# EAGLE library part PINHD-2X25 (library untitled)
PIN HEADER
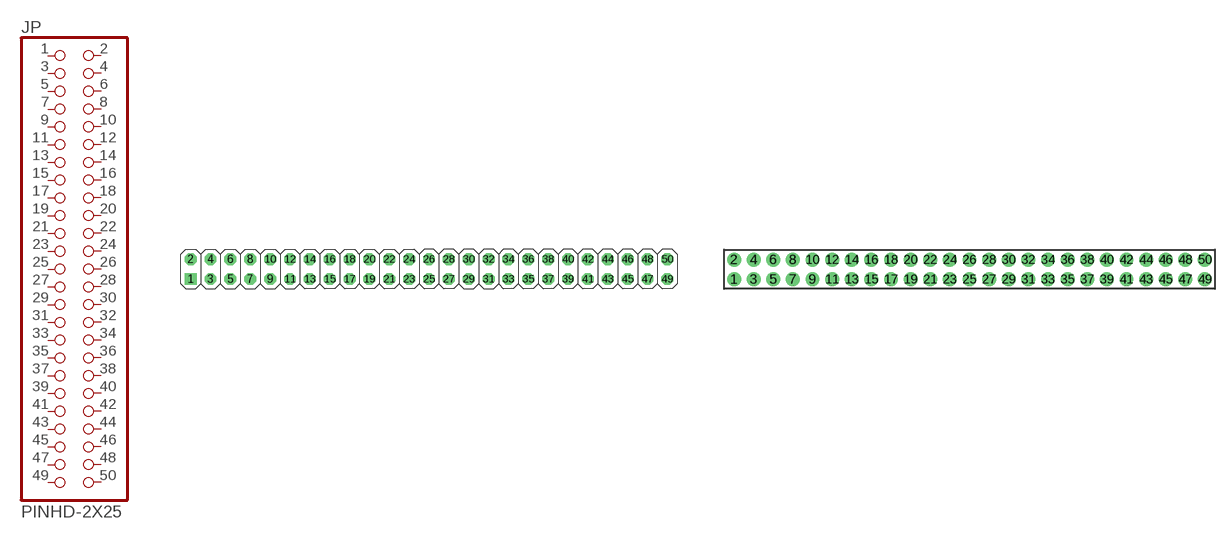
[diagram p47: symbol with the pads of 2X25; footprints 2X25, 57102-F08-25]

Designator prefix JP

## PINHD-2X25_2.54  [2X25]
1  1  pas
2  2  pas
3  3  pas
4  4  pas
5  5  pas
6  6  pas
7  7  pas
8  8  pas
9  9  pas
10  10  pas
11  11  pas
12  12  pas
13  13  pas
14  14  pas
15  15  pas
16  16  pas
17  17  pas
18  18  pas
19  19  pas
20  20  pas
21  21  pas
22  22  pas
23  23  pas
24  24  pas
25  25  pas
26  26  pas
27  27  pas
28  28  pas
29  29  pas
30  30  pas
31  31  pas
32  32  pas
33  33  pas
34  34  pas
35  35  pas
36  36  pas
37  37  pas
38  38  pas
39  39  pas
40  40  pas
41  41  pas
42  42  pas
43  43  pas
44  44  pas
45  45  pas
46  46  pas
47  47  pas
48  48  pas
49  49  pas
50  50  pas

## PINHD-2X25_57102-F08-25  [57102-F08-25]
Pads as for 2X25

## PINHD-2X25_2.54-90°  [2X25/90]
Pads as for 2X25

## PINHD-2X25_2.00  [2X25M]
Pads as for 2X25

## PINHD-2X25_2.54-SMD  [2X25SMD]
Pads as for 2X25

## PINHD-2X25_2.54-SMD-90°  [2X25SMD/90]
Pads as for 2X25

## Footprint 2X25 (pad centres in mm)
PIN HEADER - 2.54
drill 1.016 square: 1 -30.48,-1.27
drill 1.016 octagon: 2 -30.48,1.27; 3 -27.94,-1.27; 4 -27.94,1.27; 5 -25.4,-1.27; 6 -25.4,1.27; 7 -22.86,-1.27; 8 -22.86,1.27; 9 -20.32,-1.27; 10 -20.32,1.27; 11 -17.78,-1.27; 12 -17.78,1.27; 13 -15.24,-1.27; 14 -15.24,1.27; 15 -12.7,-1.27; 16 -12.7,1.27; 17 -10.16,-1.27; 18 -10.16,1.27; 19 -7.62,-1.27; 20 -7.62,1.27; 21 -5.08,-1.27; 22 -5.08,1.27; 23 -2.54,-1.27; 24 -2.54,1.27; 25 0,-1.27; 26 0,1.27; 27 2.54,-1.27; 28 2.54,1.27; 29 5.08,-1.27; 30 5.08,1.27; 31 7.62,-1.27; 32 7.62,1.27; 33 10.16,-1.27; 34 10.16,1.27; 35 12.7,-1.27; 36 12.7,1.27; 37 15.24,-1.27; 38 15.24,1.27; 39 17.78,-1.27; 40 17.78,1.27; 41 20.32,-1.27; 42 20.32,1.27; 43 22.86,-1.27; 44 22.86,1.27; 45 25.4,-1.27; 46 25.4,1.27; 47 27.94,-1.27; 48 27.94,1.27; 49 30.48,-1.27; 50 30.48,1.27

## Footprint 57102-F08-25 (pad centres in mm)
UNSH HEADER 2.0mm VERTICAL TMT Source: https://portal.fciconnect.com/res/en/pdffiles/doc_search/57102.pdf
drill 0.8 pad 1.422 round: 1 -9,-1; 2 -9,1; 3 -7,-1; 4 -7,1; 5 -5,-1; 6 -5,1; 7 -3,-1; 8 -3,1; 9 -1,-1; 10 -1,1; 11 1,-1; 12 1,1; 13 3,-1; 14 3,1; 15 5,-1; 16 5,1; 17 7,-1; 18 7,1; 19 9,-1; 20 9,1; 21 11,-1; 22 11,1; 23 13,-1; 24 13,1; 25 15,-1; 26 15,1; 27 17,-1; 28 17,1; 29 19,-1; 30 19,1; 31 21,-1; 32 21,1; 33 23,-1; 34 23,1; 35 25,-1; 36 25,1; 37 27,-1; 38 27,1; 39 29,-1; 40 29,1; 41 31,-1; 42 31,1; 43 33,-1; 44 33,1; 45 35,-1; 46 35,1; 47 37,-1; 48 37,1; 49 39,-1; 50 39,1

## Footprint 2X25/90 (pad centres in mm)
PIN HEADER - 2.54 90°
drill 1.016 square: 1 -24.13,-6.35
drill 1.016 octagon: 2 -24.13,-3.81; 3 -21.59,-6.35; 4 -21.59,-3.81; 5 -19.05,-6.35; 6 -19.05,-3.81; 7 -16.51,-6.35; 8 -16.51,-3.81; 9 -13.97,-6.35; 10 -13.97,-3.81; 11 -11.43,-6.35; 12 -11.43,-3.81; 13 -8.89,-6.35; 14 -8.89,-3.81; 15 -6.35,-6.35; 16 -6.35,-3.81; 17 -3.81,-6.35; 18 -3.81,-3.81; 19 -1.27,-6.35; 20 -1.27,-3.81; 21 1.27,-6.35; 22 1.27,-3.81; 23 3.81,-6.35; 24 3.81,-3.81; 25 6.35,-6.35; 26 6.35,-3.81; 27 8.89,-6.35; 28 8.89,-3.81; 29 11.43,-6.35; 30 11.43,-3.81; 31 13.97,-6.35; 32 13.97,-3.81; 33 16.51,-6.35; 34 16.51,-3.81; 35 19.05,-6.35; 36 19.05,-3.81; 37 21.59,-6.35; 38 21.59,-3.81; 39 24.13,-6.35; 40 24.13,-3.81; 41 26.67,-6.35; 42 26.67,-3.81; 43 29.21,-6.35; 44 29.21,-3.81; 45 31.75,-6.35; 46 31.75,-3.81; 47 34.29,-6.35; 48 34.29,-3.81; 49 36.83,-6.35; 50 36.83,-3.81

## Footprint 2X25M (pad centres in mm)
PIN HEADER - 2
drill 0.914 square: 1 -24,-1
drill 0.914 round: 2 -24,1; 3 -22,-1; 4 -22,1; 5 -20,-1; 6 -20,1; 7 -18,-1; 8 -18,1; 9 -16,-1; 10 -16,1; 11 -14,-1; 12 -14,1; 13 -12,-1; 14 -12,1; 15 -10,-1; 16 -10,1; 17 -8,-1; 18 -8,1; 19 -6,-1; 20 -6,1; 21 -4,-1; 22 -4,1; 23 -2,-1; 24 -2,1; 25 0,-1; 26 0,1; 27 2,-1; 28 2,1; 29 4,-1; 30 4,1; 31 6,-1; 32 6,1; 33 8,-1; 34 8,1; 35 10,-1; 36 10,1; 37 12,-1; 38 12,1; 39 14,-1; 40 14,1; 41 16,-1; 42 16,1; 43 18,-1; 44 18,1; 45 20,-1; 46 20,1; 47 22,-1; 48 22,1; 49 24,-1; 50 24,1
